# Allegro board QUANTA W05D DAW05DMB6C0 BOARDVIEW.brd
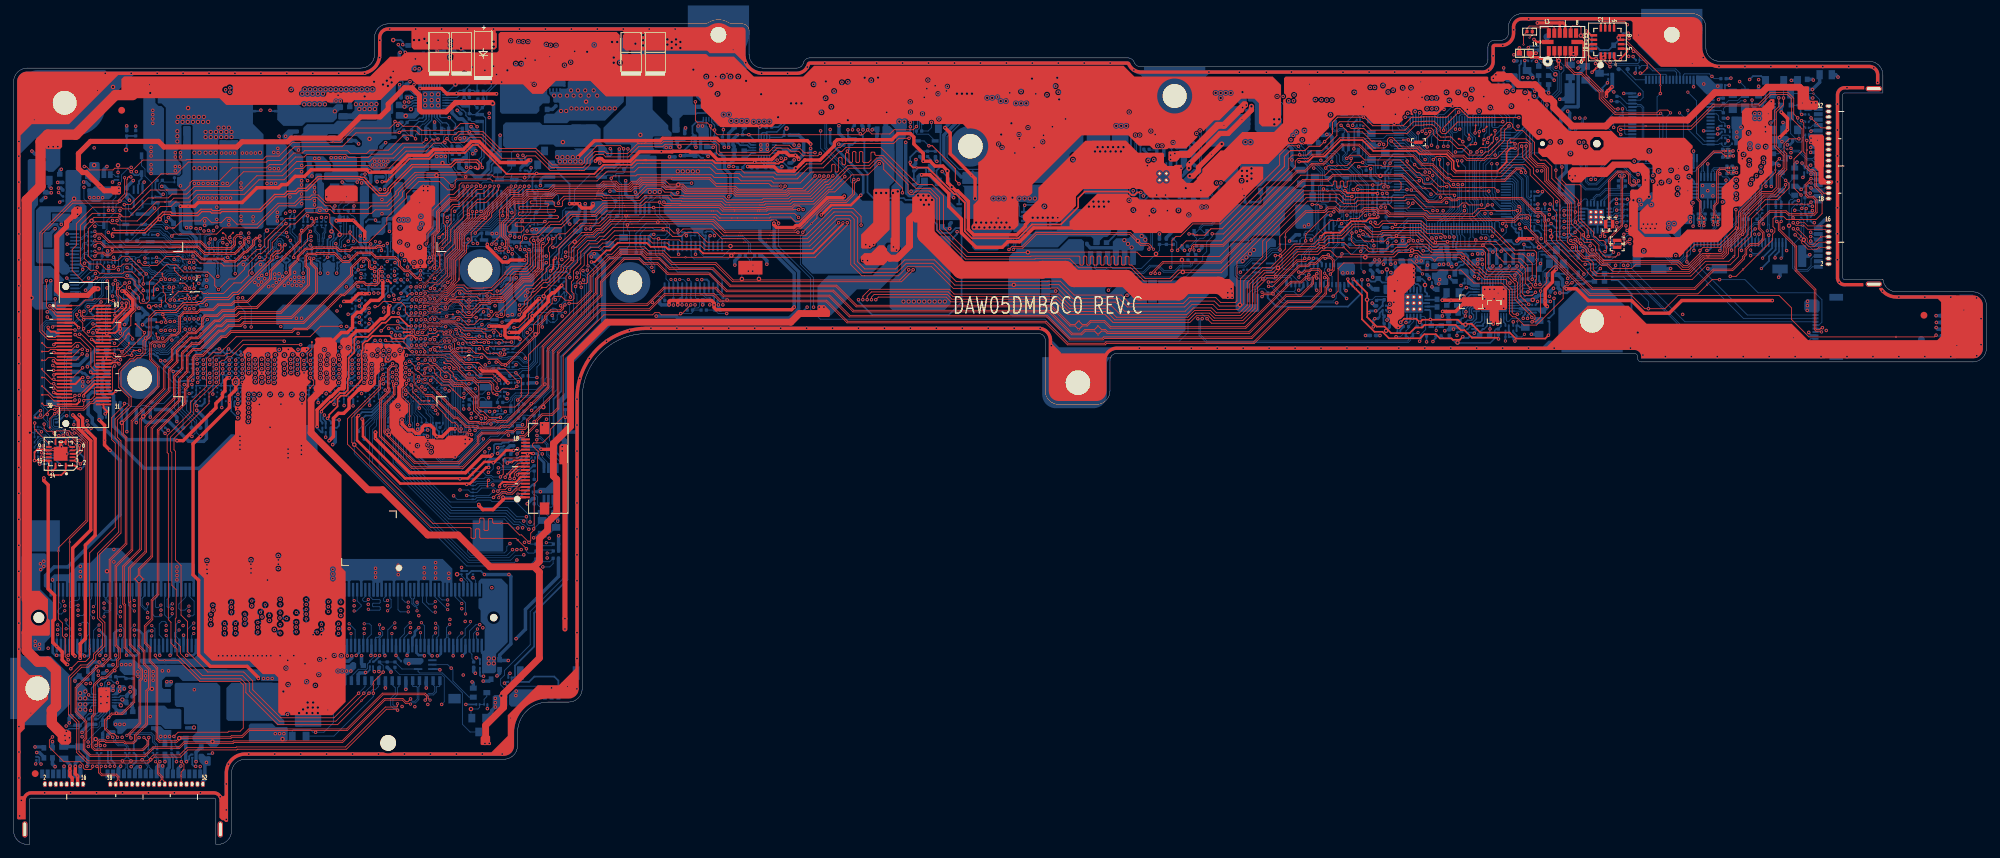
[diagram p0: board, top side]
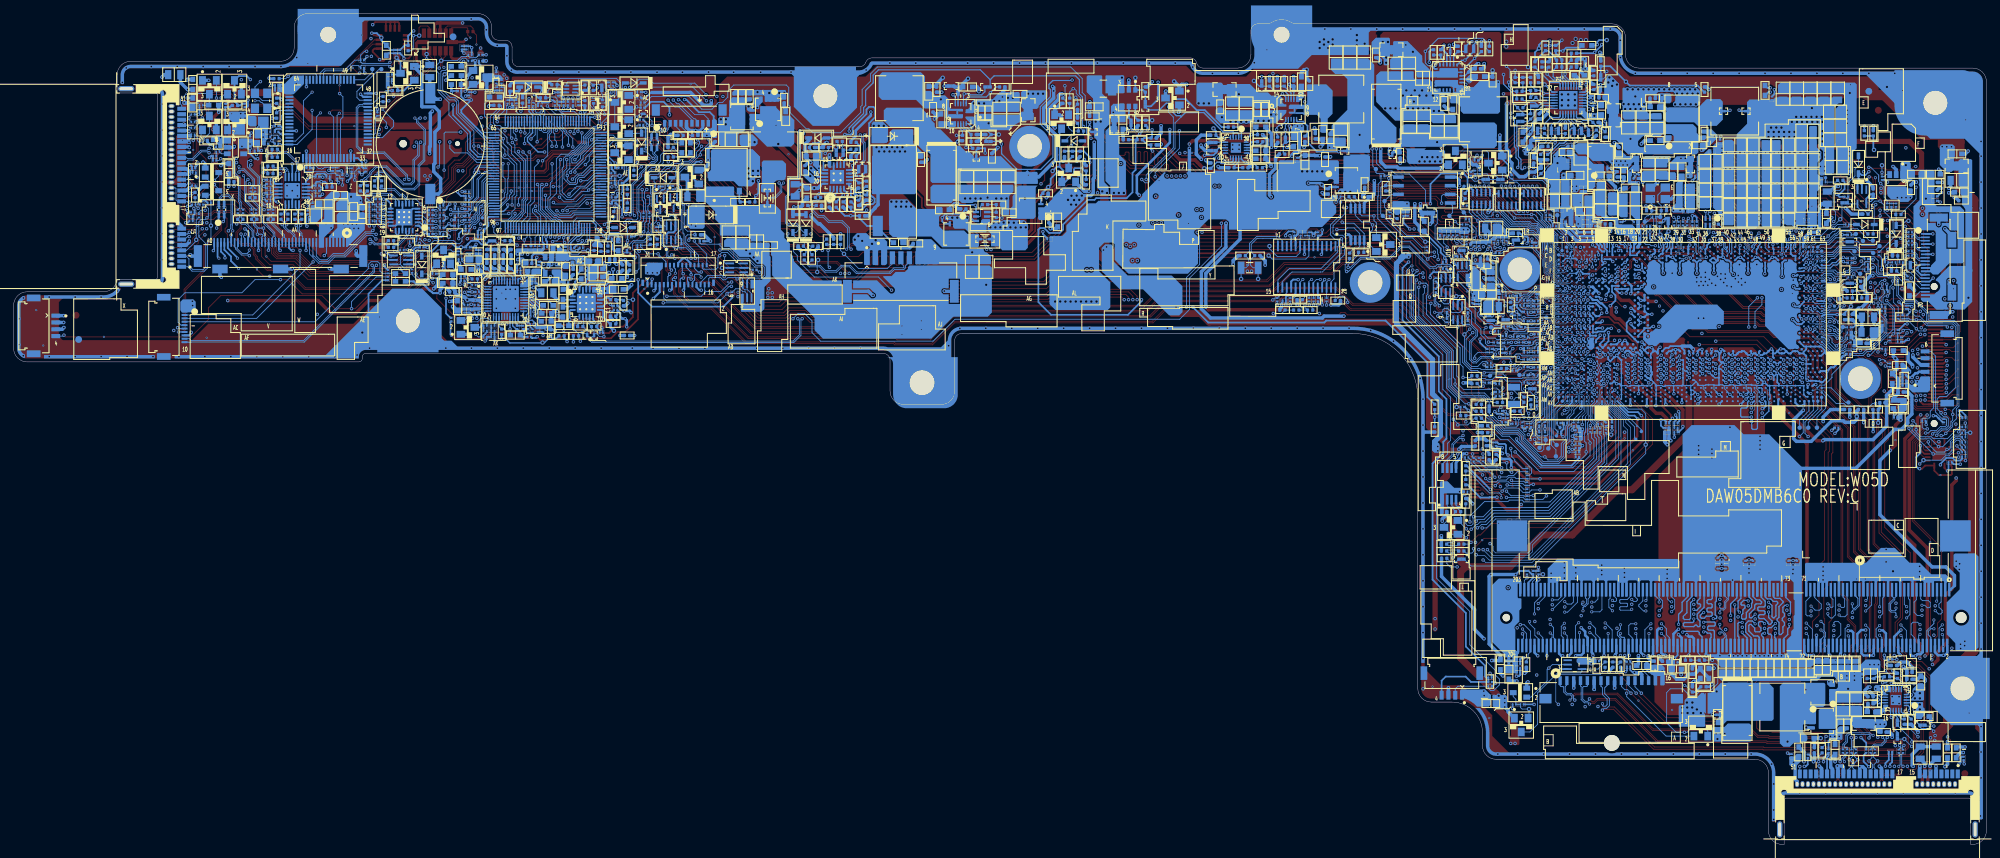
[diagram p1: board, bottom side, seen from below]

Outline 289.7 x 122 mm; copper layers: TOP, SGND, IN1, IN2, SVCC, BOTTOM. Coordinates in mm from the lower left corner of the outline.
Outline path: 0,112 arc(0.59,113.41) 2,114 51,114 arc(52.41,114.59) 53,116 53,118.5 arc(53.59,119.91) 55,120.5 101.43,120.5 arc(101.72,120.54) 101.99,120.67 arc(103.5,121.12) 105.02,120.67 arc(105.28,120.54) 105.57,120.5 107,120.5 arc(107.71,120.21) 108,119.5 108,116 arc(108.59,114.59) 110,114 115,114 arc(115.61,114.21) 115.97,114.75 arc(116.32,115.29) 116.94,115.5 163.63,115.5 arc(164.2,115.32) 164.56,114.85 arc(164.93,114.38) 165.5,114.2 215.5,114.2 arc(216.21,114.49) 216.5,115.2 216.5,117.1 arc(216.79,117.81) 217.5,118.1 218.5,118.1 arc(219.21,118.39) 219.5,119.1 219.5,120 arc(220.09,121.41) 221.5,122 246.5,122 arc(247.91,121.41) 248.5,120 248.5,117 arc(249.09,115.59) 250.5,115 272.5,115 arc(273.91,114.41) 274.5,113 274.5,110.35 268.9,110.35 arc(268.69,110.26) 268.6,110.05 268.6,83.25 arc(268.69,83.04) 268.9,82.95 274.51,82.95 arc(275.16,81.67) 276.5,81.15 287.7,81.15 arc(289.11,80.56) 289.7,79.15 289.7,72.85 arc(289.11,71.44) 287.7,70.85 239,70.85 arc(238.65,71) 238.5,71.35 238.5,71.6 arc(238.35,71.95) 238,72.1 162,72.1 arc(161.29,71.81) 161,71.1 161,66.6 arc(160.41,65.19) 159,64.6 153.5,64.6 arc(152.09,65.19) 151.5,66.6 151.5,74.02 arc(151.21,74.73) 150.5,75.02 93,75.02 arc(86.28,72.24) 83.5,65.52 83.5,22.9 arc(82.91,21.49) 81.5,20.9 78.5,20.9 arc(75.32,19.58) 74,16.4 74,14.5 arc(73.41,13.09) 72,12.5 34,12.5 arc(32.59,11.91) 32,10.5 32,2 arc(31.41,0.59) 30,0 29.7,0 29.7,6.5 arc(29.61,6.71) 29.4,6.8 2.6,6.8 arc(2.39,6.71) 2.3,6.5 2.3,0 2,0 arc(0.59,0.59) 0,2 0,112

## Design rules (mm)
constraint set DEFAULT: min track width 0.127
net group DFP-S7W7(8)-T1B: nets VCC_SENSE VSS_SENSE
net group T11B: nets DDR3_DRAMRST# SM_DRAMRST#
net group DFP-S3.5(4)W4.5-T12B: nets M_B_CLKN0 M_B_CLKN1 M_B_CLKP0 M_B_CLKP1
net group DFP-S3.5(4)W5-T12B: nets M_B_DQSN0 M_B_DQSN1 M_B_DQSN2 M_B_DQSN3 M_B_DQSN4 M_B_DQSN5 M_B_DQSN6 M_B_DQSN7 M_B_DQSP0 M_B_DQSP1 M_B_DQSP2 M_B_DQSP3 M_B_DQSP4 M_B_DQSP5 M_B_DQSP6 M_B_DQSP7
net group DFP-S4W5(4.5)-T1B: nets C_TX0_HDMI+ C_TX0_HDMI- C_TX1_HDMI+ C_TX1_HDMI- C_TX2_HDMI+ C_TX2_HDMI- C_TXC_HDMI+ C_TXC_HDMI- EDP_AUXN_R EDP_AUXP_R EDP_TXN0_R EDP_TXN1_R EDP_TXP0_R EDP_TXP1_R IN_CLK IN_CLK# IN_D0 IN_D0# IN_D1 IN_D1# IN_D2 IN_D2# INT_EDP_AUXN INT_EDP_AUXP INT_EDP_TXN0 INT_EDP_TXN1 INT_EDP_TXP0 INT_EDP_TXP1 MBCLK MBCLK2 MBDATA MBDATA2 SATA_RXN0_C SATA_RXN0_DC SATA_RXN0_DC_L SATA_RXN1 SATA_RXN1_C SATA_RXP0_C SATA_RXP0_DC SATA_RXP0_DC_L SATA_RXP1 SATA_RXP1_C SATA_TXN0 SATA_TXN0_C SATA_TXN0_DC SATA_TXN0_DC_L SATA_TXN1 SATA_TXN1_C SATA_TXP0 SATA_TXP0_C SATA_TXP0_DC SATA_TXP0_DC_L SATA_TXP1 SATA_TXP1_C SDVO_CLK SDVO_DATA SMB_ME0_CLK SMB_ME0_DAT SMB_ME1_CLK SMB_ME1_DAT SMB_PCH_CLK SMB_PCH_DAT SMB_RUN_CLK SMB_RUN_DAT USB30_RX1+ USB30_RX1+_C USB30_RX1+_DC USB30_RX1- USB30_RX1-_C USB30_RX1-_DC USB30_RX3+ USB30_RX3+_R USB30_RX3- USB30_RX3-_R USB30_TX1+ USB30_TX1+_C USB30_TX1+_DC USB30_TX1+_DC_C USB30_TX1- USB30_TX1-_C USB30_TX1-_DC USB30_TX1-_DC_C USB30_TX3+ USB30_TX3+_R USB30_TX3- USB30_TX3-_R USB+_CAMERA USB+_COMBO USB+_CR USB+_LEFT USB+_SENSOR USB+_TP USB+_TS USB+_WLAN USB-_CAMERA USB-_COMBO USB-_CR USB-_LEFT USB-_SENSOR USB-_TP USB-_TS USB-_WLAN USBP2+_C USBP2-_C USBP7+_C USBP7-_C
net group DFP-S4W5(4.5)-T12B: nets PCIE_RXN2_CARD PCIE_RXN3_WLAN PCIE_RXP2_CARD PCIE_RXP3_WLAN PCIE_TXN2_CARD PCIE_TXN2_CARD_C PCIE_TXN3_WLAN PCIE_TXN3_WLAN_C PCIE_TXP2_CARD PCIE_TXP2_CARD_C PCIE_TXP3_WLAN PCIE_TXP3_WLAN_C
net group DFP-S4W5-T12B: nets BQSRN BQSRP CSON CSOP SMC SMD
net group DFP-S8(5.5)W5(4.5)-T1B: nets CK_XDP_N CK_XDP_N_R CK_XDP_P CK_XDP_P_R CLK_PCIE_CRN CLK_PCIE_CRP CLK_PCIE_WLANN CLK_PCIE_WLANP
net group T1B: nets 3920_RST# +SMDDR_VREF_DIMM +SMDDR_VREF_DQ1 ALERT# CLK_24M_DEBUG CLK_24M_KBC CLK_PCI_EC_R CLK_PCI_LPC_R DDR_VTTREF DIGITAL_CLK DIGITAL_D1 DMIC0 DMIC_CLK_R DNBSWON# DNBSWON#_R EC_PECI EC_PECI_R EC_PWROK EC_RCIN# EXT_MIC_L FAN1_PWM FAN1SIG H_CPU_SVIDALRT# H_SYS_PWROK_XDP HOME_BUTTON_INT# HOME_BUTTON_SLEEP HPOUT_L HPOUT_L_1 HPOUT_R HPOUT_R_1 IMVP_PWRGD IMVP_PWRGD_R L_SPK+ L_SPK- LINEOUT_L LINEOUT_L_C LINEOUT_R LINEOUT_R_C MINICAR_PME# OVT_DETC PCH_INVRMEN PCH_OPI_RCOMP PCH_THRMTRIP# PCIE_CLKREQ0# PCIE_CLKREQ3# PCIE_CLKREQ4# PCIE_CLKREQ_WLAN# PCIE_WAKE# PM_THRMTRIP# R_SPK+ R_SPK- REQ_WLAN# RTC_RST# SATA_IREF SATA_RCOMP SENSE_A SENSE_A_1 SM_RCOMP_0 SM_RCOMP_1 SM_VREF SMDDR_VREF_DQ1_M1 SMDDR_VREF_DQ1_M3 SRTC_RST# SYS_PWROK SYS_RESET# THER_CPU THER_GPU THRM_ALERT_HW#1 VR_SVID_ALERT# VR_SVID_CLK VR_SVID_DATA VREFOUT_C XDP_BPM0 XDP_BPM1
net group T12B: nets 1237BSTPCH 1237ENPCH 1237FBPCH 1237FBPCH_S 1237PFMPCH 1237PGPCH 8008LX1.5V 51216DRVH 51216DRVL 51216MODE 51216PG 51216REFIN 51216S3 51216S5 51216SW 51216TRIP 51216VBST 51216VBST_S 51216VDDQSNS 81101_BST 81101_HG 81101_HG_G 81101_LG 81101_PH 81101COM 81101DIFFOUT 81101FB 81101ILIM 81101IOUT 81101ROSC 81101VCC 81101VRMP 81101VSN 81101VSP +0.75V_DDR_VTT +1.05V_S2 +1.8VREF +1.35VSUS_S +3.3VS5_S +3V_AVDD +3V_DEEP_SUS +3V_DVDD +3V_DVDD-IO +3V_RTC +3V_RTC_0 +3V_RTC_1 +3V_WLAN_P +3VLCD_CON +3VPCU +3VSPI +5VS5_S +12VALW +VCC_TS +VIN_1.05V +VIN_3VS5 +VIN_5VS5 +VIN_BLIGHT +VIN_DDR +VIN_VCC_CORE AC_LED_ON# ACIN ACZ_BCLK ACZ_RST# ACZ_RST#_AUDIO ACZ_SDIN0 ACZ_SDOUT ACZ_SDOUT_AUDIO ACZ_SPKR ACZ_SYNC ACZ_SYNC_AUDIO AD_AIR B_TEMP_MBAT BATDIS_G BATDIS_ID_DOD BIOS_CS# BIOS_RD# BIOS_SPI_CLK BIOS_WP# BIOS_WR# BIT_CLK_AUDIO BLON_CON BQACDRV BQB_1 BQB_2 BQBATDRV BQCLK BQCMSRC BQDATA BQHIDRV BQIOUT BQLODRV BQVCC CRY2 CSCOMP CSREF CSSUM EDP_RCOMP EMU_LID G5934CN G5934CP G5934DISC1 G5934DISC2 G5934DISC4 G5934PG GPIO33_EC H_PROCHOT# H_PROCHOT#_EC HD_SDIN0 IDEA_G LAD0 LAD1 LAD2 LAD3 LFRAME# M_B_DQ0 M_B_DQ1 M_B_DQ2 M_B_DQ3 M_B_DQ4 M_B_DQ5 M_B_DQ6 M_B_DQ7 M_B_DQ8 M_B_DQ9 M_B_DQ10 M_B_DQ11 M_B_DQ12 M_B_DQ13 M_B_DQ14 M_B_DQ15 M_B_DQ16 M_B_DQ17 M_B_DQ18 M_B_DQ19 M_B_DQ20 M_B_DQ21 M_B_DQ22 M_B_DQ23 M_B_DQ24 M_B_DQ25 M_B_DQ26 M_B_DQ27 M_B_DQ28 M_B_DQ29 M_B_DQ30 M_B_DQ31 M_B_DQ32 M_B_DQ33 M_B_DQ34 M_B_DQ35 M_B_DQ36 M_B_DQ37 M_B_DQ38 M_B_DQ39 M_B_DQ40 M_B_DQ41 M_B_DQ42 M_B_DQ43 M_B_DQ44 M_B_DQ45 M_B_DQ46 M_B_DQ47 M_B_DQ48 M_B_DQ49 M_B_DQ50 M_B_DQ51 M_B_DQ52 M_B_DQ53 M_B_DQ54 M_B_DQ55 M_B_DQ56 M_B_DQ57 M_B_DQ58 M_B_DQ59 M_B_DQ60 M_B_DQ61 M_B_DQ62 M_B_DQ63 M_B_ODT0 M_B_ODT1 MBATLED0# NB670BST NB670BST_S NB670EN NB670ENLDO NB670PG NB670SW NB670VOUT NB671BST NB671BST_S NB671EN NB671FB NB671PG NB671SW PCH_DPST_PWM PCH_DPST_PWM_R PCH_EDP_BLON PCH_SPI1_CLK PCH_SPI1_CLK_R PCH_SPI1_SI PCH_SPI1_SI_R PCH_SPI1_SO PCH_SPI1_SO_R PCH_SPI_CS0# PCH_SPI_CS0#_R PCH_SPI_IO2 PCH_SPI_IO3 PCIE_CLKREQ_CR# PCIE_IREF PCIE_RCOMP PROCHOT# REGN6V RTC_X1 RTC_X2 SM_INTRUDER# SM_RCOMP_2 SPKR SWN SYS_I TEMP_MBAT THRM_MOINTOR THRM_MOINTOR1 TSENSE VBOOT VR_HOT# VR_RDY XCLK_BIASREF XTAL24_IN XTAL24_OUT
net group TB: nets CATERR#
net group W4.5(5)-T1B: nets PLTRST#
net group W5(4.5)-T1B: nets I2C0_SCL I2C0_SDA I2C1_SCL I2C1_SDA SDIO_CLK SDIO_CMD SDIO_D1 SDIO_D2 SDIO_D3
net group W7.5(8)-T12B: nets M_B_A0 M_B_A1 M_B_A2 M_B_A3 M_B_A4 M_B_A5 M_B_A6 M_B_A7 M_B_A8 M_B_A9 M_B_A10 M_B_A11 M_B_A12 M_B_A13 M_B_A14 M_B_A15 M_B_BS#0 M_B_BS#1 M_B_BS#2 M_B_CAS# M_B_CKE0 M_B_CKE1 M_B_CS#0 M_B_CS#1 M_B_RAS# M_B_WE#

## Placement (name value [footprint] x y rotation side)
C1  0.22u/10v_4  [CC0402]  222.62 119.36 180 top
C2  10u/6.3v_6  [CC0603]  221.86 116.18 180 top
C3  0.1u/10v_2  [CC0201_S]  223.87 116.97 90 bottom
C4  0.1u/10v_2  [CC0201_S]  223.21 116.97 90 bottom
C5  *0.1u/10v_2  [CC0201_S]  46.86 60.53 180 bottom
C8  4.7u/25v_8  [CC0805]  228.59 113.57 90 bottom
C9  1u/6.3v_2  [CC0201_S]  218.81 113.14 270 bottom
C11  10u/6.3vs_6  [CC0603]  263.39 111.61 270 bottom
C12  4.7u/6.3v_6  [CC0603]  224.68 111.59 180 bottom
C13  0.1u/10v_2  [CC0201_S]  251.07 111.49 0 bottom
C14  0.047uf_4  [CC0402]  205.81 111.13 270 bottom
C15  1u/6.3v_2  [CC0201_S]  218.69 110.95 90 bottom
C16  1u/6.3v_2  [CC0201_S]  218.05 110.95 90 bottom
C17  0.1u/10v_2  [CC0201_S]  251.07 110.72 0 bottom
C18  0.1u/10v_2  [CC0201_S]  224.2 110.65 180 bottom
C19  220p/25v_2  [CC0201_S]  197.86 110.47 0 bottom
C20  22u/6.3vt_8  [CC0805]  27.86 110.24 270 bottom
C21  *22u/6.3vs_8  [CC0805]  25.85 110.24 270 bottom
C22  0.1u/10v_2  [CC0201_S]  222.8 110.22 90 bottom
C23  0.1u/10v_2  [CC0201_S]  209.77 110.19 270 bottom
C24  100p/50v_4  [CC0402]  214.95 109.25 270 bottom
C25  12p/50v_4  [CC0402]  251.07 109.2 90 bottom
C26  0.1u/10v_2  [CC0201_S]  216.53 109.05 270 bottom
C27  10u/6.3vs_6  [CC0603]  263.39 108.87 270 bottom
C28  0.1u/25v_4  [CC0402]  205.81 108.84 270 bottom
C29  0.1u/10v_2  [CC0201_S]  209.54 108.79 270 bottom
C30  0.1u/10v_2  [CC0201_S]  208.93 108.79 270 bottom
C31  0.1u/10v_2  [CC0201_S]  208.32 108.79 270 bottom
C32  0.1u/10v_2  [CC0201_S]  207.56 108.79 270 bottom
C33  0.01u/16v_2  [CC0201_S]  206.82 108.79 270 bottom
C34  0.1u/10v_2  [CC0201_S]  258.61 108.51 90 bottom
C35  22u/6.3vt_8  [CC0805]  22.22 107.55 0 bottom
C36  12p/50v_4  [CC0402]  251.07 107.04 270 bottom
C37  0.1u/10v_2  [CC0201_S]  251.07 105.52 180 bottom
C38  0.1u/10v_2  [CC0201_S]  251.07 104.63 0 bottom
C39  100p/50v_4  [CC0402]  191.76 104.12 0 bottom
C40  100p/50v_4  [CC0402]  189.6 104.12 180 bottom
C41  0.1u/10v_2  [CC0201_S]  254.98 103.71 90 bottom
C42  1000p/50v_4  [CC0402]  186.68 103.61 90 bottom
C43  0.1u/10v_4  [CC0402]  126.36 103.48 0 bottom
C44  1u/6.3v_4  [CC0402]  260.88 103.38 180 bottom
C45  0.1u/10v_4  [CC0402]  122.29 102.72 180 bottom
C46  22u/6.3vt_8  [CC0805]  36.95 102.72 180 bottom
C47  22u/6.3vt_8  [CC0805]  33.39 102.72 0 bottom
C48  22u/6.3vt_8  [CC0805]  29.84 102.72 180 bottom
C49  22u/6.3vt_8  [CC0805]  26.28 102.72 0 bottom
C50  *1u/6.3v_2  [CC0201_S]  61.13 102.6 0 bottom
C51  *33p/50v_4  [CC0402]  193.21 102.34 180 bottom
C52  *0.01u/10v_4  [CC0402]  251.35 102.06 0 bottom
C53  1u/6.3v_2  [CC0201_S]  254.07 101.88 180 bottom
C54  0.1u/50v_6  [CC0603]  4.34 101.4 180 bottom
C55  *220p/25v_2  [CC0201_S]  260.19 101.1 180 bottom
C56  *33p/50v_4  [CC0402]  193.21 100.94 180 bottom
C57  *0.01u/10v_4  [CC0402]  251.35 100.92 0 bottom
C58  1u/6.3v_2  [CC0201_S]  61.13 100.46 0 bottom
C59  22u/6.3vt_8  [CC0805]  36.95 100.44 180 bottom
C60  22u/6.3vt_8  [CC0805]  33.39 100.44 0 bottom
C61  22u/6.3vt_8  [CC0805]  29.84 100.44 180 bottom
C62  22u/6.3vt_8  [CC0805]  26.28 100.44 0 bottom
C63  22u/6.3vt_8  [CC0805]  40.51 100.31 0 bottom
C64  *0.01u/10v_4  [CC0402]  251.99 99.6 0 bottom
C65  0.1u/10v_2  [CC0201_S]  201.64 99.37 0 bottom
C66  *47p/25v_2  [CC0201_S]  200.6 99.37 0 bottom
C67  0.1u/10v_2  [CC0201_S]  246.45 99.34 0 bottom
C68  0.1u/10v_2  [CC0201_S]  263.26 99.29 180 bottom
C69  *10u/6.3v_6  [CC0603]  258.11 99.24 270 bottom
C70  47u/6.3vst_8  [CC0805]  49.65 99.07 270 bottom
C71  47u/6.3vst_8  [CC0805]  47.62 99.07 270 bottom
C72  0.1u/10v_2  [CC0201_S]  237.99 99.04 270 bottom
C73  0.01u/16v_2  [CC0201_S]  263.19 98.66 180 bottom
C74  *0.01u/10v_4  [CC0402]  251.99 98.51 0 bottom
C75  *10u/6.3v_6  [CC0603]  7.51 98.4 0 bottom
C76  1u/6.3v_2  [CC0201_S]  43.05 98.15 180 bottom
C77  22u/6.3vt_8  [CC0805]  40.51 98.15 0 bottom
C78  22u/6.3vt_8  [CC0805]  36.95 98.15 180 bottom
C79  22u/6.3vt_8  [CC0805]  33.39 98.15 0 bottom
C80  22u/6.3vt_8  [CC0805]  29.84 98.15 180 bottom
C81  22u/6.3vt_8  [CC0805]  26.28 98.15 0 bottom
C82  1u/6.3v_2  [CC0201_S]  51.05 98.1 270 bottom
C83  0.1u/10v_2  [CC0201_S]  245.1 98.07 0 bottom
C84  1u/6.3v_2  [CC0201_S]  243.53 98.07 0 bottom
C85  1u/6.3v_2  [CC0201_S]  51.81 97.52 90 bottom
C86  *4.7u/25v_8  [CC0805]  4.36 97.52 180 bottom
C87  0.1u/10v_4  [CC0402]  257.73 97.34 0 bottom
C88  *0.047u/10v_4  [CC0402]  7.59 97.21 180 bottom
C89  0.1u/10v_2  [CC0201_S]  201.67 97.13 180 bottom
C90  *0.1u/10v_4  [CC0402]  236.69 97.06 90 bottom
C91  *0.1u/10v_4  [CC0402]  235.68 97.06 90 bottom
C92  *0.1u/10v_2  [CC0201_S]  263.24 96.75 180 bottom
C93  22u/6.3vst_8  [CC0805]  62.6 96.63 0 bottom
C94  1u/6.3v_4  [CC0402]  11.07 96.45 90 bottom
C95  *47u/6.3vst_8  [CC0805]  44.19 96.37 0 bottom
C96  *0.1u/10v_4  [CC0402]  238.78 96.35 90 bottom
C97  *0.1u/10v_4  [CC0402]  237.76 96.35 90 bottom
C98  22p/50v_4  [CC0402]  88.21 96.35 90 bottom
C99  1u/6.3v_2  [CC0201_S]  59.48 96.2 270 bottom
C100  *1u/6.3v_2  [CC0201_S]  58.87 96.2 270 bottom
C101  0.1u/10v_2  [CC0201_S]  254.88 96.12 90 bottom
C102  0.1u/10v_2  [CC0201_S]  254.25 96.12 90 bottom
C103  22u/6.3vt_8  [CC0805]  40.51 96.12 0 bottom
C104  *0.047u/10v_4  [CC0402]  7.61 96.09 180 bottom
C105  22u/6.3vt_8  [CC0805]  36.95 95.99 180 bottom
C106  *22u/6.3vs_8  [CC0805]  33.39 95.99 0 bottom
C107  *22u/6.3vs_8  [CC0805]  29.84 95.99 180 bottom
C108  22u/6.3vt_8  [CC0805]  26.28 95.99 0 bottom
C109  *0.1u/10v_4  [CC0402]  16.63 95.86 90 bottom
C110  0.1u/50v_6  [CC0603]  3.95 95.79 0 bottom
C111  0.01u/25v_4  [CC0402]  241.67 95.36 0 bottom
C112  *10p/25v_2  [CC0201_S]  223.08 95.23 180 bottom
C113  0.01u/16v_2  [CC0201_S]  7.54 95.15 0 bottom
C114  2200p/50v_4  [CC0402]  93.21 95.1 180 bottom
C115  0.01u/25v_4  [CC0402]  91.18 95.1 180 bottom
C116  22u/6.3vs_8  [CC0805]  55.87 95.08 180 bottom
C117  47u/6.3vst_8  [CC0805]  52.32 94.77 180 bottom
C118  *0.1u/10v_2  [CC0201_S]  236.21 94.75 0 bottom
C119  *10p/25v_2  [CC0201_S]  223.08 94.59 180 bottom
C120  *22u/6.3vs_8  [CC0805]  59.25 94.57 180 bottom
C121  .01u/25v_4  [CC0402]  3.68 94.54 180 bottom
C122  *0.01u/16v_2  [CC0201_S]  7.54 94.52 180 bottom
C123  22u/6.3vs_8  [CC0805]  62.7 94.44 0 bottom
C124  *47u/6.3vst_8  [CC0805]  44.19 94.34 0 bottom
C125  0.1u/10v_2  [CC0201_S]  201.59 94.14 0 bottom
C126  0.1u/50v_6  [CC0603]  244.09 94.09 0 bottom
C127  22u/6.3vt_8  [CC0805]  40.51 94.09 0 bottom
C128  *33p/25v_2  [CC0201_S]  263.24 93.93 180 bottom
C129  22u/6.3vt_8  [CC0805]  36.95 93.83 180 bottom
C130  22u/6.3vt_8  [CC0805]  33.39 93.83 0 bottom
C131  22u/6.3vt_8  [CC0805]  29.84 93.83 180 bottom
C132  22u/6.3vt_8  [CC0805]  26.28 93.83 0 bottom
C133  *10p/50v_4  [CC0402]  199.59 93.81 90 bottom
C134  *10p/25v_2  [CC0201_S]  223.08 93.32 180 bottom
C135  1u/6.3v_2  [CC0201_S]  62.6 93.07 0 bottom
C136  22u/6.3vs_8  [CC0805]  55.87 93.07 180 bottom
C137  12p/50v_4  [CC0402]  49.52 93.07 180 bottom
C138  12p/50v_4  [CC0402]  47.36 93.07 0 bottom
C139  10u/6.3vs_6  [CC0603]  59.02 92.97 180 bottom
C140  0.1u/10v_2  [CC0201_S]  256.79 92.94 90 bottom
C141  0.1u/10v_2  [CC0201_S]  256.02 92.94 90 bottom
C142  0.1u/10v_2  [CC0201_S]  254.75 92.94 90 bottom
C143  0.1u/10v_2  [CC0201_S]  254.12 92.94 90 bottom
C144  0.1u/10v_2  [CC0201_S]  252.34 92.94 90 bottom
C145  0.1u/10v_2  [CC0201_S]  251.58 92.94 90 bottom
C146  *4.7u/25v_8  [CC0805]  241.6 92.94 270 bottom
C147  0.1u/50v_6  [CC0603]  239.77 92.94 90 bottom
C148  0.01u/25v_4  [CC0402]  238.5 92.94 270 bottom
C149  1u/6.3v_2  [CC0201_S]  44.19 92.94 0 bottom
C150  0.1u/10v_2  [CC0201_S]  263.36 92.82 0 bottom
C151  47u/6.3vs_8  [CC0805]  52.32 92.77 180 bottom
C152  0.1u/10v_2  [CC0201_S]  85.59 92.56 90 bottom
C153  1u/6.3v_2  [CC0201_S]  84.96 92.56 270 bottom
C154  *10p/50v_4  [CC0402]  17.77 92.56 0 bottom
C155  *10p/25v_2  [CC0201_S]  223.08 92.33 180 bottom
C156  *4.7u/25v_8  [CC0805]  244.47 92.31 180 bottom
C157  0.1u/10v_2  [CC0201_S]  263.64 92.18 0 bottom
C158  *0.01u/10v_4  [CC0402]  250.44 92.18 90 bottom
C159  *0.01u/10v_4  [CC0402]  249.42 92.18 90 bottom
C160  *0.01u/10v_4  [CC0402]  248.4 92.18 90 bottom
C161  *0.01u/10v_4  [CC0402]  247.39 92.18 90 bottom
C162  1u/6.3v_2  [CC0201_S]  58.89 92 180 bottom
C163  4.7u/6.3v_6  [CC0603]  23.49 91.93 90 bottom
C164  22u/6.3vt_8  [CC0805]  36.95 91.67 180 bottom
C165  *22u/6.3vs_8  [CC0805]  33.39 91.67 0 bottom
C166  22u/6.3vt_8  [CC0805]  29.84 91.67 180 bottom
C167  0.1u/10v_2  [CC0201_S]  263.64 91.55 0 bottom
C168  1u/6.3v_2  [CC0201_S]  58.89 91.39 180 bottom
C169  1u/6.3v_2  [CC0201_S]  53.99 91.39 180 bottom
C170  1u/6.3v_2  [CC0201_S]  51.5 91.39 180 bottom
C171  0.1u/10v_2  [CC0201_S]  45.84 91.17 270 bottom
C172  0.1u/10v_2  [CC0201_S]  45.2 91.17 270 bottom
C173  0.1u/10v_2  [CC0201_S]  44.57 91.17 270 bottom
C174  0.1u/10v_2  [CC0201_S]  43.93 91.17 270 bottom
C175  1u/6.3v_2  [CC0201_S]  58.89 90.78 180 bottom
C176  1u/6.3v_2  [CC0201_S]  57.7 90.78 0 bottom
C177  22u/6.3vst_8  [CC0805]  72.71 90.51 0 bottom
C178  0.1u/10v_2  [CC0201_S]  11.17 89.9 180 bottom
C179  0.1u/10v_2  [CC0201_S]  221.28 89.82 180 bottom
C180  *0.1u/10v_2  [CC0201_S]  228.47 89.64 180 bottom
C181  *0.1u/10v_2  [CC0201_S]  101.62 89.64 270 bottom
C182  *0.1u/10v_2  [CC0201_S]  98.16 89.64 270 bottom
C183  0.1u/10v_2  [CC0201_S]  11.17 89.26 180 bottom
C184  0.1u/10v_2  [CC0201_S]  221.28 89.18 180 bottom
C185  0.1u/10v_2  [CC0201_S]  202.1 88.96 180 bottom
C186  *0.1u/10v_2  [CC0201_S]  67.56 88.83 180 bottom
C187  *0.1u/10v_4  [CC0402]  234.28 88.65 180 bottom
C188  0.1u/10v_2  [CC0201_S]  11.17 88.63 180 bottom
C189  0.01u/25v_2  [CC0201_S]  197.86 87.99 0 bottom
C190  0.1u/10v_2  [CC0201_S]  11.17 87.99 180 bottom
C191  4.7u/6.3v_6  [CC0603]  200.91 87.91 270 bottom
C192  0.1u/10v_2  [CC0201_S]  211.6 87.74 0 bottom
C193  *0.1u/10v_4  [CC0402]  234.28 87.69 180 bottom
C194  0.1u/10v_2  [CC0201_S]  222.98 87.69 180 bottom
C195  0.1u/10v_2  [CC0201_S]  207.64 87.61 0 bottom
C196  0.047u/10v_4  [CC0402]  210.03 87.51 180 bottom
C197  *22p/50v_4  [CC0402]  203.45 87.48 90 bottom
C198  0.1u/10v_2  [CC0201_S]  11.17 87.1 180 bottom
C199  1u/6.3v_2  [CC0201_S]  221.78 87.03 270 bottom
C200  0.1u/10v_2  [CC0201_S]  221.15 87.03 270 bottom
C201  0.1u/10v_2  [CC0201_S]  208.65 87.48 270 bottom
C202  *12p  [CC0402]  109.21 86.47 180 bottom
C203  *12p  [CC0402]  107.05 86.47 0 bottom
C204  0.1u/10v_2  [CC0201_S]  11.17 86.47 180 bottom
C205  22p/50v_4  [CC0402]  13.4 86.42 0 bottom
C206  *1000p/50v_4  [CC0402]  201.8 85.96 0 bottom
C207  1u/6.3v_2  [CC0201_S]  207.64 85.83 90 bottom
C208  *10p/50v_4  [CC0402]  73.27 85.58 90 bottom
C209  1u/6.3v_2  [CC0201_S]  212.59 85.32 270 bottom
C210  2200p/50v_4  [CC0402]  220.21 84.94 270 bottom
C211  2200p/50v_4  [CC0402]  219.07 84.94 270 bottom
C212  2200p/50v_4  [CC0402]  217.8 84.94 270 bottom
C213  2200p/50v_4  [CC0402]  216.65 84.94 270 bottom
C214  *1000p/50v_4  [CC0402]  200.27 84.71 270 bottom
C215  *1000p/50v_4  [CC0402]  199.26 84.71 270 bottom
C216  1u/6.3v_2  [CC0201_S]  215.51 84.64 180 bottom
C217  1u/25v_6  [CC0603]  203.9 84.51 180 bottom
C218  4.7u/6.3v_6  [CC0603]  223.26 84.43 180 bottom
C219  22p/50v_4  [CC0402]  13.56 84.21 180 bottom
C220  0.1u/10v_2  [CC0201_S]  234.74 84.1 90 bottom
C221  *1000p/50v_4  [CC0402]  207.54 84.05 270 bottom
C222  0.1u/10v_2  [CC0201_S]  215.51 84.03 180 bottom
C223  1u/25v_8s  [CC0603]  206.34 83.77 90 bottom
C224  10p/25v_2  [CC0201_S]  223.77 83.42 180 bottom
C225  1u/10v_6  [CC0603]  203.9 83.34 180 bottom
C226  1u/25v_6  [CC0603]  201.11 83.11 180 bottom
C227  1u/6.3v_2  [CC0201_S]  213.33 83.04 0 bottom
C228  10p/25v_2  [CC0201_S]  223.77 82.78 180 bottom
C229  2.2u/6.3v_6  [CC0603]  210.94 82.68 0 bottom
C230  220p/25v_2  [CC0201_S]  234.74 83.09 90 bottom
C231  0.1u/10v_2  [CC0201_S]  208.53 82.53 0 bottom
C232  0.1u/10v_2  [CC0201_S]  213.33 82.4 0 bottom
C233  1u/6.3v_2  [CC0201_S]  71.57 81.64 90 bottom
C234  1u/25v_8s  [CC0603]  200.91 81.51 180 bottom
C235  *0.1u/10v_4  [CC0402]  20.06 81.26 0 bottom
C236  0.1u/10v_4  [CC0402]  225.29 81.13 180 bottom
C237  *10p/25v_2  [CC0201_S]  221.61 81.13 0 bottom
C238  4.7u/25v_8  [CC0805]  211.32 81.01 180 bottom
C239  *33p/25v_2  [CC0201_S]  222.93 80.9 90 bottom
C240  1u/10v_8s  [CC0603]  209.03 80.78 270 bottom
C241  0.1u/10v_2  [CC0201_S]  71.57 80.62 270 bottom
C242  *0.1u/10v_2  [CC0201_S]  98.16 79.99 90 bottom
C243  *0.1u/10v_2  [CC0201_S]  103.12 79.86 180 bottom
C244  1u/6.3v_2  [CC0201_S]  75.48 79.76 270 bottom
C245  *0.1u/10v_2  [CC0201_S]  74.87 79.58 270 bottom
C246  *1000p/50v_4  [CC0402]  200.14 79.48 270 bottom
C247  *33p/25v_2  [CC0201_S]  223.26 79.23 0 bottom
C248  2.2u/6.3v_6  [CC0603]  211.19 79.15 0 bottom
C249  22u/6.3vst_8  [CC0805]  72.51 78.97 180 bottom
C250  0.1u/10v_2  [CC0201_S]  11.8 78.87 90 bottom
C251  *10p/50v_4  [CC0402]  103.37 78.47 0 bottom
C252  0.1u/10v_2  [CC0201_S]  223.51 78.34 90 bottom
C253  1u/6.3v_2  [CC0201_S]  222.88 78.34 90 bottom
C254  1u/10v_8s  [CC0603]  209.03 78.19 90 bottom
C255  *10p/25v_2  [CC0201_S]  221.73 78.08 0 bottom
C256  2.2u/6.3v_6  [CC0603]  211.4 77.98 180 bottom
C257  *1000p/50v_4  [CC0402]  201.67 77.58 0 bottom
C258  *1u/6.3v_4  [CC0402]  19.68 77.45 90 bottom
C259  *22u/6.3v_8  [CC0805]  17.39 77.45 0 bottom
C260  0.1u/10v_2  [CC0201_S]  11.68 77.45 90 bottom
C261  2.2u/6.3v_6  [CC0603]  211.5 76.81 180 bottom
C262  0.1u/10v_2  [CC0201_S]  15.28 76.56 90 bottom
C263  0.1u/10v_2  [CC0201_S]  219.32 76.18 0 bottom
C264  1u/25v_8s  [CC0603]  208.91 76.18 0 bottom
C265  1u/6.3v_2  [CC0201_S]  214.88 75.93 90 bottom
C266  1u/6.3v_2  [CC0201_S]  214.22 75.93 90 bottom
C267  1u/6.3v_2  [CC0201_S]  213.48 75.39 90 bottom
C268  1u/6.3v_2  [CC0201_S]  212.74 75.52 90 bottom
C269  0.1u/10v_2  [CC0201_S]  212.08 75.52 90 bottom
C270  0.1u/10v_2  [CC0201_S]  220.46 75.42 0 bottom
C271  0.01u/25v_2  [CC0201_S]  219.32 75.42 0 bottom
C272  2.2u/6.3v_6  [CC0603]  216.02 74.78 0 bottom
C273  *1000p/50v_4  [CC0402]  199.61 74.73 0 bottom
C274  0.1u/10v_2  [CC0201_S]  12.79 73.82 180 bottom
C275  *0.1u/10v_2  [CC0201_S]  70.81 72.73 180 bottom
C276  220p/25v_2  [CC0201_S]  12.06 68.94 180 bottom
C277  0.1u/10v_2  [CC0201_S]  12.06 68.05 0 bottom
C278  10p/25v_4  [CC0402]  66.9 64.93 90 bottom
C279  0.022u/6.3v_4  [CC0402]  15.26 64.88 180 bottom
C280  *2.2u/6.3v_6  [CC0603]  12.95 64.01 180 bottom
C281  10p/25v_4  [CC0402]  68.9 63.63 180 bottom
C282  *0.1u/10v_2  [CC0201_S]  13.33 62.69 180 bottom
C283  220p/25v_2  [CC0201_S]  9.19 62.21 0 bottom
C284  220p/25v_2  [CC0201_S]  6.22 62.21 90 bottom
C285  0.1u/10v_2  [CC0201_S]  46.83 61.83 180 bottom
C286  1u/6.3v_2  [CC0201_S]  45.59 61.83 0 bottom
C287  *1u/6.3v_2  [CC0201_S]  54.98 61.7 90 bottom
C288  1u/6.3v_2  [CC0201_S]  46.86 61.17 0 bottom
C289  0.1u/10v_2  [CC0201_S]  45.59 61.17 180 bottom
C290  0.1u/10v_2  [CC0201_S]  60.06 60.81 180 bottom
C291  1u/6.3v_2  [CC0201_S]  45.59 60.53 0 bottom
C292  1u/6.3v_2  [CC0201_S]  59.94 60.18 180 bottom
C293  0.1u/10v_2  [CC0201_S]  59.94 59.54 180 bottom
C294  1u/6.3v_2  [CC0201_S]  72.03 58.78 90 bottom
C295  0.1u/10v_2  [CC0201_S]  5.33 56.11 180 bottom
C296  *10p/50v_4  [CC0402]  76.45 50.4 90 bottom
C297  *0.01u/16v_4  [CC0402]  79.62 48.87 0 bottom
C298  *2200p/50v_4  [CC0402]  77.59 48.87 0 bottom
C299  1u/6.3v_2  [CC0201_S]  39.49 41.76 270 bottom
C300  1u/6.3v_2  [CC0201_S]  38.22 41.76 270 bottom
C301  1u/6.3v_2  [CC0201_S]  35.43 41.38 270 bottom
C302  1u/6.3v_2  [CC0201_S]  34.28 41.38 270 bottom
C303  1u/6.3v_2  [CC0201_S]  29.08 41.38 270 bottom
C304  1u/6.3v_2  [CC0201_S]  27.81 41.38 270 bottom
C305  1u/6.3v_2  [CC0201_S]  39.49 40.75 90 bottom
C306  1u/6.3v_2  [CC0201_S]  38.22 40.75 90 bottom
C307  0.1u/10v_2  [CC0201_S]  66.57 39.91 270 bottom
C308  1u/6.3v_2  [CC0201_S]  68.71 27.16 0 bottom
C309  *0.1u/10v_2  [CC0201_S]  14.09 27.16 0 bottom
C310  *0.1u/10v_2  [CC0201_S]  57.14 26.9 0 bottom
C311  *220p/25v_2  [CC0201_S]  52.54 26.83 180 bottom
C312  *0.1u/10v_2  [CC0201_S]  45.61 26.73 0 bottom
C313  1u/6.3v_2  [CC0201_S]  68.71 26.52 0 bottom
C314  0.1u/10v_4  [CC0402]  48.76 26.52 270 bottom
C315  2.2u/6.3v_4  [CC0402]  22.34 26.52 90 bottom
C316  2.2u/6.3v_4  [CC0402]  21.33 26.52 90 bottom
C317  2.2u/6.3v_4  [CC0402]  20.31 26.52 90 bottom
C318  2.2u/6.3v_4  [CC0402]  19.22 26.52 90 bottom
C319  2.2u/6.3v_6  [CC0603]  71.37 26.4 90 bottom
C320  *10u/6.3v_6  [CC0603]  50.61 26.27 180 bottom
C321  10u/6.3v_6  [CC0603]  24.68 26.27 90 bottom
C322  10u/6.3v_6  [CC0603]  23.49 26.27 90 bottom
C323  0.1u/10v_2  [CC0201_S]  52.54 26.12 0 bottom
C324  1u/6.3v_2  [CC0201_S]  68.71 25.89 0 bottom
C325  10u/6.3v_6  [CC0603]  38.8 25.89 90 bottom
C326  10u/6.3v_6  [CC0603]  37.63 25.89 90 bottom
C327  10u/6.3v_6  [CC0603]  36.47 25.89 90 bottom
C328  10u/6.3v_6  [CC0603]  35.27 25.89 90 bottom
C329  10u/6.3v_6  [CC0603]  34.1 25.89 90 bottom
C330  10u/6.3v_6  [CC0603]  32.94 25.89 90 bottom
C331  10u/6.3v_6  [CC0603]  31.77 25.89 90 bottom
C332  10u/6.3v_6  [CC0603]  30.6 25.89 90 bottom
C333  10u/6.3v_6  [CC0603]  29.43 25.89 90 bottom
C334  10u/6.3v_6  [CC0603]  28.26 25.89 90 bottom
C335  10u/6.3v_6  [CC0603]  27.07 25.89 90 bottom
C336  10u/6.3v_6  [CC0603]  25.87 25.89 90 bottom
C337  *2.2u/6.3v_6  [CC0603]  45.51 25.76 0 bottom
C338  1u/6.3v_2  [CC0201_S]  68.71 25.25 0 bottom
C339  10u/6.3v_6  [CC0603]  70.12 25 90 bottom
C340  *220p/25v_2  [CC0201_S]  72.89 23.86 0 bottom
C341  *220p/25v_2  [CC0201_S]  72.89 23.22 0 bottom
C342  0.022u/6.3v_4  [CC0402]  43.17 22.76 90 bottom
C343  0.1u/10v_2  [CC0201_S]  72.64 21.7 180 bottom
C344  10u/6.3vs_6  [CC0603]  72.76 20.68 0 bottom
C345  0.1u/10v_2  [CC0201_S]  69.33 20.55 0 bottom
C346  4.7u/6.3v_6  [CC0603]  22.22 13.95 270 bottom
C347  0.01u/16v_2  [CC0201_S]  23.18 13.7 270 bottom
C348  *0.1u/16v_2  [CC0201_S]  21.07 13.7 270 bottom
C349  *0.1u/16v_2  [CC0201_S]  20.44 13.7 270 bottom
C350  0.01u/16v_2  [CC0201_S]  19.8 13.7 90 bottom
C351  0.01u/16v_2  [CC0201_S]  19.17 13.7 90 bottom
C352  0.01u/16v_2  [CC0201_S]  17.65 13.7 270 bottom
C353  0.01u/16v_2  [CC0201_S]  17.01 13.7 90 bottom
C354  0.01u/16v_2  [CC0201_S]  16.38 13.7 90 bottom
C355  4.7u/6.3v_6  [CC0603]  27.55 13.57 270 bottom
C356  *4.7u/6.3v_6  [CC0603]  5.71 13.44 270 bottom
C357  *4.7u/6.3v_6  [CC0603]  4.44 13.44 270 bottom
C358  0.01u/16v_2  [CC0201_S]  28.59 13.01 270 bottom
C359  *0.1u/10v_2  [CC0201_S]  26.23 12.96 270 bottom
C360  0.01u/16v_2  [CC0201_S]  3.34 12.63 270 bottom
C361  *1000p/50v_4  [CC0402]  209.24 74.68 180 bottom
C362  10u/6.3v_6  [CC0603]  234.97 116.62 90 bottom
C363  0.01u/16v_4  [CC0402]  231.77 116.95 270 bottom
C364  0.1u/10v_2  [CC0201_S]  232.96 116.41 90 bottom
C365  0.1u/10v_2  [CC0201_S]  233.6 116.41 90 bottom
C366  22u/6.3vs_8  [CC0805]  266.11 113.04 180 bottom
CN1  *sec_bsh-030-01-l-d-a-tr  [BSH-030-01-L-D-A-TR-60P-LDH]  10.33 71.86 270 top
CN2  *aces_88511-180n  [88511-180N-18P-L]  77.97 55.22 90 top
CN3  camera conn  [50208-01001-001-10P-L]  190.49 107.85 0 bottom
CN4  rtc_conn  [ML1220-SMT]  228.51 102.9 90 bottom
CN5  mini pcie h=4.0  [MINIPCI-MPCET-SSC10-TS10-52P]  273.17 96.63 270 bottom
CN6  gs12407-11141-9f  [GS12407-11141-9H-40P-R]  250.5 86.4 180 bottom
CN7  gs12401-1011-9h  [50406-02071-001-20P-R]  7 84.9 90 bottom
CN8  fh35c-31s-0.3shw(50)  [FH35C-31S-0_3SHW-31P-LDH]  192.12 83.67 180 bottom
CN9  pmpcr0-08mnbs2zz4h5  [51278-00941-001-9P-L]  159.4 81.22 180 bottom
CN10  power btn conn  [50505-00441-001-4P-L]  286.75 76.15 270 bottom
CN11  touch screen  [88194-1001-10P-L]  267.65 76 270 bottom
CN12  touch screen  [50505-00641-V01-6P-L]  5.75 69.9 90 bottom
CN13  usb ffc conn  [196090-16021-3-16P-L-SMT]  55.1 21.4 180 bottom
CN14  mini sata h=4.0  [MINIPCI-MPCET-SSC10-TS10-52P]  16 2.2 180 bottom
D1  bat54c  [SOT23_213-3_3-2]  221.23 112.63 270 bottom
D2  *1ss355  [DSM]  198.54 111.82 90 bottom
D3  1ss355  [DSM]  214.06 111.21 90 bottom
D4  mek500v-40  [DSM]  197.48 103.1 180 bottom
D5  rb501v-40  [DSM]  18.79 99.8 180 bottom
D6  *ch501h-40pt  [DSM]  194.35 97.9 270 bottom
D7  *rb501v-40  [DSM]  17.77 91.04 90 bottom
D8  0.1u/10v_2  [DSM]  200.12 90.58 90 bottom
D9  rb500v-40  [DSM]  13.25 89.57 180 bottom
D10  mek500v-40  [DSM]  229.76 85.07 180 bottom
EC1  *0.1u/10v_2  [CC0201_S]  31.49 109.58 270 bottom
EC2  *0.1u/10v_2  [CC0201_S]  39.11 103.23 90 bottom
EC3  *0.1u/10v_2  [CC0201_S]  40.28 101.71 0 bottom
EC4  *0.1u/10v_2  [CC0201_S]  101.21 100.59 270 bottom
EC5  *0.1u/10v_2  [CC0201_S]  74.92 100.44 180 bottom
EC6  *0.1u/10v_2  [CC0201_S]  24.2 98.1 90 bottom
EC7  *0.1u/10v_2  [CC0201_S]  26.41 91.67 0 bottom
EC8  *0.1u/10v_2  [CC0201_S]  80.26 89.77 90 bottom
EC9  *0.1u/10v_2  [CC0201_S]  137.66 88.88 180 bottom
EC10  18p/50v_4  [CC0402]  100.83 79.99 0 bottom
EC11  *0.1u/10v_2  [CC0201_S]  12.06 67.42 180 bottom
EC12  *0.1u/10v_2  [CC0201_S]  3.29 62.59 0 bottom
EC13  18p/50v_4  [CC0402]  79.65 44.1 0 bottom
EC14  18p/50v_4  [CC0402]  79.65 43.08 0 bottom
EC15  *0.1u/10v_2  [CC0201_S]  14.09 13.57 180 bottom
FAN1  power btn conn  [50505-00441-001-4P-L]  78.5 25.15 0 bottom
H1  *h-te354x299bc91d91p2  [H-TE354X299BC91D91P2]  243.5 118.9 180 bottom
H2  *h-te354x339bc91d91p2  [H-TE354X339BC91D91P2]  103.5 118.9 180 bottom
H3  h-te354x339bc138d138p2  [H-TE354X339BC138D138P2]  170.5 109.9 180 bottom
H4  h-te473x378bc138d138p2  [H-TE473X378BC138D138P2]  7.5 108.9 180 bottom
H5  h-tc236ic142bc142d142p2  [H-TC236IC142BC142D142P2]  140.5 102.52 180 bottom
H6  h-tc236ic142bc142d142p2  [H-TC236IC142BC142D142P2]  68.5 84.4 180 bottom
H7  h-tc236ic142bc142d142p2  [H-TC236IC142BC142D142P2]  90.5 82.52 180 bottom
H8  h-te354x366bc138d138p2  [H-TE354X366BC138D138P2]  231.8 76.9 180 bottom
H9  h-tc236ic142bc142d142p2  [H-TC236IC142BC142D142P2]  18.5 68.4 180 bottom
H10  h-te413x295bc142d142p2  [H-TE413X295BC142D142P2]  156.3 67.8 180 bottom
H11  h-te315x354bc138d138p2  [H-TE315X354BC138D138P2]  3.5 22.9 180 bottom
H14  *h-c91d91n  [H-C91D91N]  55 14.9 0 top
JDIM1  ddr3-dimm1_h=4.0_rvs  [DDR-DDRRK-20401-TP4B-204P-RUV]  37.1 33.3 180 bottom
L1  blm18ba470sn1d  [RC0603]  224.68 112.91 180 bottom
L2  *mcm2012b900gbe  [CHOKE-WCM2012-4P]  195.62 103.1 270 bottom
L3  fcm1608kf-301t02  [RC0603]  191.58 102.29 270 bottom
L4  fcm1608kf-301t02  [RC0603]  190.31 102.29 270 bottom
L5  *0_8/s  [SHORT0805]  4.36 99.62 180 bottom
L6  2.2uh/500ma_6  [RC0603]  45.97 98.79 270 bottom
L7  0_6  [RC0603]  44.7 98.79 270 bottom
L8  ti160808u600  [RC0603]  10.28 98.4 180 bottom
L9  2.2uh/500ma_6  [RC0603]  60.39 98.25 180 bottom
L10  2.2uh/500ma_6  [RC0603]  57.22 96.78 0 bottom
L11  2.2uh/500ma_6  [RC0603]  52.32 96.37 180 bottom
L12  *mcm2012b900gbe  [CHOKE-WCM2012-4P]  259.17 93.2 90 bottom
L13  blm18pg181sn1d(180,1.5a)_6  [RC0603]  204.54 85.68 180 bottom
L14  0_6  [RC0603]  213.48 84.18 180 bottom
L15  *0_6  [RC0603]  208.63 84.18 270 bottom
L16  hcb1608kf-181t15_6  [RC0603]  225.93 83.67 0 bottom
L17  *hcb1608kf-181t15_6  [RC0603]  225.93 82.4 0 bottom
L18  hcb1608kf-181t15_6  [RC0603]  224.53 79.1 90 bottom
NOREF  -  []  -0.9 -30.75 0 top
NOREF#2  -  []  52.19 44.96 0 top
NOREF#3  -  []  159.05 -17.7 0 top
NOREF#4  -  []  22.98 46.08 180 bottom
PC1  *15u 25v  [CC3528]  62.48 116.31 270 top
PC2  *15u 25v  [CC3528]  65.78 116.31 270 top
PC3  *15u 25v  [CC3528]  90.67 116.31 270 top
PC4  15u 25v  [CC3528]  94.23 116.31 270 top
PC5  *0.1u/10v_4  [CC0402]  77.59 116.82 90 bottom
PC6  0.1u/10v_4  [CC0402]  74.16 116.82 270 bottom
PC7  0.1u/25v_4  [CC0402]  89.65 115.93 90 bottom
PC8  22u/6.3v_8  [CC0805]  95.5 115.55 270 bottom
PC9  22u/6.3v_8  [CC0805]  93.46 115.55 270 bottom
PC10  22u/6.3v_8  [CC0805]  91.43 115.55 270 bottom
PC11  *680p/50v_4  [CC0402]  62.73 115.17 0 bottom
PC12  1000p/50v_4  [CC0402]  60.57 115.17 180 bottom
PC13  470p/50v_4  [CC0402]  65.27 114.53 270 bottom
PC14  270p/50v_4  [CC0402]  62.73 114.15 0 bottom
PC15  4.7u/25v_8  [CC0805]  86.86 113.9 90 bottom
PC16  4.7u/25v_8  [CC0805]  84.83 113.9 90 bottom
PC17  1u/6.3v_4  [CC0402]  74.67 113.9 180 bottom
PC18  2.2u/6.3v_6  [CC0603]  59.78 112.96 180 bottom
PC19  2200p/50v_4  [CC0402]  83.3 112.5 270 bottom
PC20  0.1u/25v_4  [CC0402]  82.29 112.5 270 bottom
PC21  0.1u/25v_4  [CC0402]  72.51 112.25 90 bottom
PC22  *1500p/50v_4  [CC0402]  68.06 112.25 270 bottom
PC23  *0.1u/10v_4  [CC0402]  105.28 111.74 90 bottom
PC24  1u/6.3v_4  [CC0402]  101.72 111.74 90 bottom
PC25  0.1u/25v_4  [CC0402]  99.43 111.74 90 bottom
PC26  10u/6.3v_6  [CC0603]  149.6 111.23 180 bottom
PC27  0.01u/25v_4  [CC0402]  57.65 111.23 270 bottom
PC28  *2200p/50v_4  [CC0402]  154.17 110.85 270 bottom
PC29  0.1u/10v_4  [CC0402]  123.51 110.85 90 bottom
PC30  10p/50v_4  [CC0402]  66.54 110.72 0 bottom
PC31  330p/50v_4  [CC0402]  68.57 110.6 0 bottom
PC32  *22u/6.3v_8  [CC0805]  29.86 110.24 270 bottom
PC33  *22u/6.3v_8  [CC0805]  23.84 110.24 270 bottom
PC34  *22u/6.3v_8  [CC0805]  21.84 110.24 270 bottom
PC35  0.1u/25v_4  [CC0402]  141.91 110.22 180 bottom
PC36  2200p/50v_4  [CC0402]  183.89 109.83 270 bottom
PC37  1000p/50v_4  [CC0402]  182.75 109.83 270 bottom
PC38  0.1u/25v_4  [CC0402]  181.6 109.83 90 bottom
PC39  0.1u/25v_4  [CC0402]  56.51 109.63 180 bottom
PC40  *2200p/50v_4  [CC0402]  49.01 109.58 180 bottom
PC41  *2200p/50v_4  [CC0402]  176.55 109.28 270 bottom
PC42  *2200p/50v_4  [CC0402]  79.62 108.82 90 bottom
PC43  0.01u/25v_4  [CC0402]  218.79 108.54 0 bottom
PC44  0.1u/10v_4  [CC0402]  133.47 108.31 90 bottom
PC45  10u/6.3v_6  [CC0603]  131.01 108.31 180 bottom
PC46  0.1u/25v_4  [CC0402]  112.51 108.31 90 bottom
PC47  *2200p/50v_4  [CC0402]  68.45 108.18 0 bottom
PC48  4.7u/25v_8  [CC0805]  110.74 108.06 90 bottom
PC49  4.7u/25v_8  [CC0805]  108.7 108.06 90 bottom
PC50  0.1u/25v_4  [CC0402]  154.68 107.93 270 bottom
PC51  0.1u/25v_4  [CC0402]  107.08 107.93 270 bottom
PC52  2200p/50v_4  [CC0402]  105.94 107.93 270 bottom
PC53  0.22u/25v_6  [CC0603]  56.51 107.83 270 bottom
PC54  0.1u/25v_4  [CC0402]  147.57 107.42 90 bottom
PC55  2200p/50v_4  [CC0402]  146.55 107.42 90 bottom
PC56  4.7u/25v_8  [CC0805]  144.9 107.29 270 bottom
PC57  4.7u/25v_8  [CC0805]  142.87 107.29 270 bottom
PC58  *220uf_6.3v_7343  [CC7343-2_15H]  88.13 107.24 90 bottom
PC59  0.1u/10v_4  [CC0402]  131.31 106.91 0 bottom
PC60  1000p/50v_4  [CC0402]  66.92 106.91 90 bottom
PC61  1u/6.3v_4  [CC0402]  65.65 106.91 90 bottom
PC62  22u/6.3v_8  [CC0805]  84.68 106.15 270 bottom
PC63  *22u/6.3v_8  [CC0805]  82.64 106.15 270 bottom
PC64  0.01u/50v_4  [CC0402]  57.4 106.02 0 bottom
PC65  *4.7u/25v_8  [CC0805]  52.57 106.02 270 bottom
PC66  4.7u/25v_8  [CC0805]  50.41 106.02 270 bottom
PC67  4.7u/25v_8  [CC0805]  48.38 106.02 270 bottom
PC68  4.7u/6.3v_6  [CC0603]  126.81 105.77 90 bottom
PC69  22u/6.3v_8  [CC0805]  80.61 105.52 270 bottom
PC70  22u/6.3v_8  [CC0805]  78.58 105.52 270 bottom
PC71  *22u/6.3v_8  [CC0805]  22.22 105.52 0 bottom
PC72  *22u/6.3v_8  [CC0805]  26.28 104.75 0 bottom
PC73  *0.1u/10v_4  [CC0402]  146.55 104.25 0 bottom
PC74  0.1u/25v_4  [CC0402]  41.39 104.25 270 bottom
PC75  0.1u/25v_4  [CC0402]  106.65 104.22 180 bottom
PC76  22u/6.3v_8  [CC0805]  94.81 104.12 90 bottom
PC77  *2200p/50v_4  [CC0402]  98.54 103.99 90 bottom
PC78  0.1u/10v_4  [CC0402]  96.33 103.94 90 bottom
PC79  1u/6.3v_4  [CC0402]  150.36 103.74 270 bottom
PC80  *0.1u/10v_4  [CC0402]  100.07 103.61 90 bottom
PC81  4.7u/25v_8  [CC0805]  183.51 103.48 0 bottom
PC82  *22u/6.3v_8  [CC0805]  22.22 103.48 0 bottom
PC83  0.1u/25v_4  [CC0402]  168.39 103.23 0 bottom
PC84  10u/6.3v_6  [CC0603]  101.72 103.23 270 bottom
PC85  0.1u/25v_4  [CC0402]  106.65 103.18 180 bottom
PC86  2200p/50v_4  [CC0402]  42.16 102.67 180 bottom
PC87  1u/16v_4  [CC0402]  172.46 102.34 180 bottom
PC88  0.1u/25v_4  [CC0402]  170.43 102.34 180 bottom
PC89  0.1u/25v_4  [CC0402]  166.36 102.09 0 bottom
PC90  0.1u/10v_4  [CC0402]  53.97 101.96 270 bottom
PC91  1u/35v_6  [CC0603]  106.55 101.86 0 bottom
PC92  0.1u/10v_4  [CC0402]  61.71 101.68 180 bottom
PC93  *22u/6.3v_8  [CC0805]  21.96 101.45 0 bottom
PC94  0.1u/10v_4  [CC0402]  86.1 101.2 90 bottom
PC95  0.1u/10v_4  [CC0402]  146.04 101.07 270 bottom
PC96  0.47u/25v_6  [CC0603]  106.55 100.69 180 bottom
PC97  0.1u/25v_4  [CC0402]  156.46 100.56 90 bottom
PC98  0.1u/10v_4  [CC0402]  97.12 100.56 270 bottom
PC99  *10u/6.3v_6  [CC0603]  100.07 100.46 270 bottom
PC100  0.1u/10v_4  [CC0402]  66.46 100.44 270 bottom
PC101  1u/16v_4  [CC0402]  113.89 99.67 270 bottom
PC102  *22u/6.3v_8  [CC0805]  21.96 99.42 0 bottom
PC103  0.047u/25v_4  [CC0402]  173.47 99.29 90 bottom
PC104  *0.01u/25v_4  [CC0402]  54.22 98.4 90 bottom
PC105  *0.1u/10v_4  [CC0402]  53.21 98.4 90 bottom
PC106  *220uf_6.3v_7343  [CC7343-2_15H]  153.43 98.28 270 bottom
PC107  *10u/6.3v_6  [CC0603]  56.13 98.15 0 bottom
PC108  22u/6.3v_8  [CC0805]  149.73 97.26 90 bottom
PC109  22u/6.3v_8  [CC0805]  147.69 97.26 90 bottom
PC110  22u/6.3v_8  [CC0805]  145.66 97.26 90 bottom
PC111  22u/6.3v_8  [CC0805]  143.63 97.26 90 bottom
PC112  0.1u/10v_4  [CC0402]  91.31 96.88 270 bottom
PC113  100p/50v_4  [CC0402]  165.6 96.75 90 bottom
PC114  0.022u/50v_4  [CC0402]  96.66 95.89 90 bottom
PC115  0.47u/25v_6  [CC0603]  173.22 95.64 90 bottom
PC116  2200p/50v_4  [CC0402]  138.17 95.61 0 bottom
PC117  0.1u/25v_4  [CC0402]  171.57 95 180 bottom
PC118  0.01u/50v_4  [CC0402]  164.46 94.98 90 bottom
PC119  2200p/50v_4  [CC0402]  183.38 94.34 180 bottom
PC120  *0.1u/10v_4  [CC0402]  165.6 94.21 90 bottom
PC121  0.1u/25v_4  [CC0402]  173.47 93.83 180 bottom
PC122  0.1u/25v_4  [CC0402]  171.44 93.83 180 bottom
PC123  0.1u/10v_4  [CC0402]  143.5 92.82 0 bottom
PC124  *2200p/50v_4  [CC0402]  165.09 92.31 180 bottom
PC125  0.1u/10v_4  [CC0402]  137.66 91.67 90 bottom
PC126  *10u/6.3v_6  [CC0603]  136.39 91.42 90 bottom
PC127  10u/25v_8  [CC0805]  184.65 89.13 90 bottom
PC128  10u/25v_8  [CC0805]  182.62 89.13 90 bottom
PC129  0.1u/25v_4  [CC0402]  181.09 88.5 90 bottom
PC130  0.1u/25v_4  [CC0402]  180.08 88.5 90 bottom
PC131  0.01u/25v_4  [CC0402]  168.27 88.5 90 bottom
PC132  0.022u/50v_6  [CC0603]  159.76 88.37 180 bottom
PC133  0.1u/25v_4  [CC0402]  157.22 88.24 180 bottom
PC134  0.1u/25v_4  [CC0402]  178.55 87.99 180 bottom
PC135  *100p/50v_4  [CC0402]  174.11 87.86 180 bottom
PC136  *100p/50v_4  [CC0402]  171.95 87.86 0 bottom
PC137  *0.1u/10v_4  [CC0402]  13.58 26.27 180 bottom
PC138  0.01u/25v_4  [CC0402]  16.5 24.74 270 bottom
PC139  0.1u/10v_4  [CC0402]  13.07 24.74 270 bottom
PC140  0.22u/10v_4  [CC0402]  11.3 24.24 180 bottom
PC141  10u/6.3v_6  [CC0603]  9.64 23.98 270 bottom
PC142  1u/6.3v_4  [CC0402]  17.01 21.7 180 bottom
PC143  0.1u/25v_4  [CC0402]  17.01 20.68 0 bottom
PC144  4.7u/25v_8  [CC0805]  21.07 20.55 270 bottom
PC145  4.7u/25v_8  [CC0805]  19.07 20.55 270 bottom
PC146  330u_2v_7343  [CC7343-2_15H]  36.57 19.66 270 bottom
PC147  *10u/6.3v_6  [CC0603]  9.14 18.78 0 bottom
PC148  0.1u/10v_4  [CC0402]  39.49 17.38 90 bottom
PC149  0.1u/25v_4  [CC0402]  21.46 17.38 270 bottom
PC150  2200p/50v_4  [CC0402]  20.44 17.38 270 bottom
PC151  0.1u/25v_4  [CC0402]  15.11 16.49 0 bottom
PC152  *2200p/50v_4  [CC0402]  25.27 13.82 270 bottom
PD1  p4smaj20a  [D-DO-214AC]  68.96 116.11 90 top
PD2  *bat54c  [SOT23_213-3_3-2]  119.52 109.61 90 bottom
PD3  p4smaj20a  [D-DO-214AC]  160.65 103.99 0 bottom
PD4  rb501v-40  [DSM]  171.65 103.74 270 bottom
PD5  mew316-d3-g  [DSM]  134.03 103.31 270 bottom
PD6  sx34  [D-DO-214AC]  187.27 92.44 0 bottom
PD7  pdz5.6b  [DSM]  175.25 91.17 180 bottom
PD8  pdz5.6b  [DSM]  173.35 91.17 180 bottom
PJP1  *power_jp/s  [SHORT-SOLDERJUMPER-3]  83.81 102.47 270 bottom
PJP2  *power_jp/s  [SHORT-SOLDERJUMPER-3]  92.07 101.58 270 bottom
PJP3  *power_jp/s  [SHORT-SOLDERJUMPER-3]  140.84 97.01 270 bottom
PJP4  *power_jp/s  [SHORT-SOLDERJUMPER-3]  40.94 20.73 0 bottom
PL1  *0_8/s  [SHORT0805]  87.37 116.69 180 bottom
PL2  2.2uh/1.3a_2520  [L3_2X2_5-1_55]  129.66 110.98 0 bottom
PL3  *0_8/s  [SHORT0805]  111.88 110.85 180 bottom
PL4  4.7uh/5.5a  [CHOKE-MPL73-1R5]  159.63 109.58 270 bottom
PL5  4.7uh/5.5a  [CHOKE-MPL73-1R5]  94.73 109.45 180 bottom
PL6  *0_8/s  [SHORT0805]  140.71 107.81 270 bottom
PL7  0.22uh/29a_7x7x1.8  [CHOKE-ETQP4LR36AFM]  36.95 107.68 180 bottom
PL8  *0_8/s  [SHORT0805]  54.75 107.07 90 bottom
PL9  1uh/11a(em-10am05v06)  [CHOKE-MPL73-1R5]  73.88 106.48 270 bottom
PL10  80/5a  [RC0805]  59.56 101.45 270 bottom
PL11  4.7uh/5.5a(em-47am05v08)  [CHOKE-MPL73-1R5]  178.05 101.33 270 bottom
PL12  80/5a  [RC0805]  148.94 84.82 270 bottom
PL13  80/5a  [RC0805]  146.91 84.82 270 bottom
PL14  0.82uh/13a(em-82bm05v04)  [CHOKE-MPL73-1R5]  29.96 20.17 0 bottom
PL15  *0_8/s  [SHORT0805]  18.03 17.76 0 bottom
PQ1  emb20n03v  [PG-TSDSON-8-8P-R]  178.91 107.93 180 bottom
PQ2  emb20n03v  [PG-TSDSON-8-8P-R]  182.75 106.79 270 bottom
PQ3  rjk03s3dpa  [POWER-5X6-1_27-7P]  44.7 106.61 180 bottom
PQ4  *metr3904-g  [SOT23_213-3_3-2]  135.81 106.13 0 bottom
PQ5  *emb20n03v  [PG-TSDSON-8-8P-R]  56.63 100.82 0 bottom
PQ6  tpca8064-h  [SO-8FL-5P]  185.03 99.67 0 bottom
PQ7  qm3016d  [TO252_134-9_9-4_57-SMT]  160.52 98.91 270 bottom
PQ8  *2n7002k  [SOT23_213-3_3-2]  134.76 98.3 180 bottom
PQ9  2n7002k  [SOT23_213-3_3-2]  190.11 98 90 bottom
PQ10  emb20n03v  [PG-TSDSON-8-8P-R]  93.97 97.52 90 bottom
PQ11  emb20n03v  [PG-TSDSON-8-8P-R]  140.35 93.05 270 bottom
PQ12  mmdt2907a  [SOT363-2_1-65-6P]  147.57 92.21 0 bottom
PQ13  emb20p03v  [PG-TSDSON-8-8P-R]  151.25 89.64 180 bottom
PQ14  mdv1595surh  [PG-TSDSON-8-8P-R]  24.12 22.33 270 bottom
PQ15  emb20n03v  [PG-TSDSON-8-8P-R]  24.12 18.14 90 bottom
PR1  287k/f_6  [RC0603]  58.67 117.33 0 bottom
PR2  121k/f_4  [RC0402]  64.76 116.95 270 bottom
PR3  165k/f_4  [RC0402]  63.24 116.95 270 bottom
PR4  *0_4/s  [SHORT0402]  76.45 116.82 90 bottom
PR5  *0_4/s  [SHORT0402]  75.3 116.82 90 bottom
PR6  100k/f_4  [RC0402]  72.99 116.82 90 bottom
PR7  *0_2/s  [SHORT0201]  78.73 116.44 90 bottom
PR8  2.4k/f_4  [RC0402]  81.17 116.31 270 bottom
PR9  7.68k/f_4  [RC0402]  80.13 116.31 270 bottom
PR10  10/f_4  [RC0402]  60.57 116.18 0 bottom
PR11  8.25k/f_4  [RC0402]  56.63 114.66 90 bottom
PR12  15.4k/f_4  [RC0402]  66.29 114.53 90 bottom
PR13  24.3k/f_4  [RC0402]  64.25 114.53 90 bottom
PR14  100k/f_4  [RC0402]  60.57 114.15 180 bottom
PR15  69.8k/f_4  [RC0402]  57.65 113.26 270 bottom
PR16  0_6  [RC0603]  74.41 112.76 180 bottom
PR17  *0_4/s  [SHORT0402]  56.63 112.63 90 bottom
PR18  0_4  [RC0402]  69.21 112.25 270 bottom
PR19  6.04k/f_4  [RC0402]  66.92 112.25 90 bottom
PR20  18.7k/f_4  [RC0402]  65.78 112.25 90 bottom
PR21  0_6  [RC0603]  100.58 111.99 90 bottom
PR22  *0_4/s  [SHORT0402]  106.42 111.74 90 bottom
PR23  *330k/f_4  [RC0402]  104.13 111.74 270 bottom
PR24  *665k/f_4  [RC0402]  103.12 111.74 90 bottom
PR25  *0_4/s  [SHORT0402]  152.01 111.36 0 bottom
PR26  *0_4/s  [SHORT0402]  146.68 111.23 180 bottom
PR27  *0_4  [RC0402]  144.52 111.23 0 bottom
PR28  th05-3l104fr  [RC0402]  41.39 110.85 270 bottom
PR29  220k_6 ntc  [RC0603]  32.5 110.72 90 bottom
PR30  *2.2_6  [RC0603]  155.31 110.6 90 bottom
PR31  1k/f_4  [RC0402]  66.54 109.71 180 bottom
PR32  49.9/f_4  [RC0402]  68.57 109.45 180 bottom
PR33  *1m_4  [RC0402]  135.63 109.2 90 bottom
PR34  *1m_4  [RC0402]  134.61 109.2 90 bottom
PR35  *0_4/s  [SHORT0402]  123.51 108.69 270 bottom
PR36  *2.2_6  [RC0603]  78.35 108.67 270 bottom
PR37  *0_4/s  [SHORT0402]  66.41 108.44 0 bottom
PR38  *2.2_6  [RC0603]  48.63 108.31 0 bottom
PR39  *0_2/s  [SHORT0201]  38.6 107.68 0 bottom
PR40  *0_2/s  [SHORT0201]  35.3 107.68 180 bottom
PR41  *0_4/s  [SHORT0402]  68.45 107.17 0 bottom
PR42  *2.2_6  [RC0603]  176.32 106.89 90 bottom
PR43  0_6  [RC0603]  153.54 106.53 90 bottom
PR44  12.4k/f_4  [RC0402]  133.47 106.28 270 bottom
PR45  *0_4/s  [SHORT0402]  68.45 106.15 0 bottom
PR46  *0_4/s  [SHORT0402]  125.61 105.97 270 bottom
PR47  10k/f_4  [RC0402]  124.59 105.95 270 bottom
PR48  15k/f_4  [RC0402]  123.45 105.95 270 bottom
PR49  *0_6/s  [SHORT0603]  128.08 105.77 270 bottom
PR50  22_6  [RC0603]  106.55 105.36 0 bottom
PR51  *0_4  [RC0402]  110.94 105.34 180 bottom
PR52  *0_4/s  [SHORT0402]  65.91 104.78 270 bottom
PR53  *0_4  [RC0402]  64.89 104.78 270 bottom
PR54  *0_4/s  [SHORT0402]  63.87 104.78 270 bottom
PR55  *0_4/s  [SHORT0402]  62.86 104.78 270 bottom
PR56  *0_4/s  [SHORT0402]  60.52 104.78 270 bottom
PR57  *0_4/s  [SHORT0402]  59.45 104.78 270 bottom
PR58  75k/f_4  [RC0402]  132.96 104.75 180 bottom
PR59  *0_2/s  [SHORT0201]  131.18 104.63 0 bottom
PR60  *0_4/s  [SHORT0402]  58.44 104.5 270 bottom
PR61  *10k/f_4  [RC0402]  57.27 104.5 90 bottom
PR62  *330k/f_4  [RC0402]  148.71 104.25 0 bottom
PR63  *2.2_6  [RC0603]  97.45 104.25 270 bottom
PR64  1k/f_4  [RC0402]  56 104.25 90 bottom
PR65  *0_4  [RC0402]  113.53 104.15 0 bottom
PR66  2.2_6  [RC0603]  68.06 103.87 270 bottom
PR67  *0_4  [RC0402]  104.08 103.48 90 bottom
PR68  *0_4/s  [SHORT0402]  102.94 103.48 270 bottom
PR69  1_6  [RC0603]  48.63 103.36 0 bottom
PR70  *665k/f_4  [RC0402]  148.71 103.23 180 bottom
PR71  *0_4/s  [SHORT0402]  146.55 103.23 180 bottom
PR72  100k/f_4  [RC0402]  166.36 103.1 180 bottom
PR73  *0_4/s  [SHORT0402]  113.53 103.08 180 bottom
PR74  *0_4/s  [SHORT0402]  66.92 102.98 90 bottom
PR75  *75/f_4  [RC0402]  64.76 102.49 0 bottom
PR76  *82k/f_4  [RC0402]  148.46 102.21 180 bottom
PR77  *0_4/s  [SHORT0402]  113.48 101.88 0 bottom
PR78  *0_2/s  [SHORT0201]  94.23 101.83 180 bottom
PR79  *0_4/s  [SHORT0402]  168.9 101.58 270 bottom
PR80  *0_4/s  [SHORT0402]  167.89 101.58 270 bottom
PR81  69.8k/f_4  [RC0402]  135.37 101.4 90 bottom
PR82  *88.7k/f_4  [RC0402]  134.21 101.4 90 bottom
PR83  430k/f_4  [RC0402]  133.09 101.4 270 bottom
PR84  10k/f_4  [RC0402]  103.42 101.38 0 bottom
PR85  *0_2/s  [SHORT0201]  87.24 101.33 90 bottom
PR86  0_6  [RC0603]  172.59 101.07 0 bottom
PR87  *100k/f_4  [RC0402]  166.36 101.07 180 bottom
PR88  *0_2/s  [SHORT0201]  148.33 100.94 270 bottom
PR89  130/f_4  [RC0402]  65.45 100.94 270 bottom
PR90  *75/f_4  [RC0402]  64.43 100.94 270 bottom
PR91  *100k/f_4  [RC0402]  110.86 99.37 0 bottom
PR92  *750k/f_4  [RC0402]  108.81 99.37 0 bottom
PR93  *0_4  [RC0402]  106.7 99.37 180 bottom
PR94  *1m_4  [RC0402]  132.2 99.29 90 bottom
PR95  *0_4/s  [SHORT0402]  165.6 99.17 90 bottom
PR96  *0_4/s  [SHORT0402]  164.58 99.17 90 bottom
PR97  54.9/f_4  [RC0402]  65.4 98.91 90 bottom
PR98  *1m_4  [RC0402]  132.2 97.26 270 bottom
PR99  10/f_4  [RC0402]  164.46 97.01 270 bottom
PR100  22_8  [RC0805]  174.92 96.04 270 bottom
PR101  *0_2/s  [SHORT0201]  179.02 95.61 90 bottom
PR102  470_8  [RC0805]  189.86 95.1 180 bottom
PR103  rc1206-r020  [F3_2X1_65-2_8]  179.02 94.87 270 bottom
PR104  2k/f_4  [RC0402]  181.22 94.34 0 bottom
PR105  *0_2/s  [SHORT0201]  179.02 94.21 270 bottom
PR106  4.02k/f_4  [RC0402]  169.92 93.96 90 bottom
PR107  2k/f_4  [RC0402]  168.9 93.96 90 bottom
PR108  100k/f_4  [RC0402]  167.89 93.96 90 bottom
PR109  100k/f_4  [RC0402]  166.74 93.96 270 bottom
PR110  220k_4  [RC0402]  147.06 93.96 180 bottom
PR111  1m_4  [RC0402]  145.03 93.96 180 bottom
PR112  1m_4  [RC0402]  150.23 93.32 0 bottom
PR113  1k_6  [RC0603]  153.03 93.2 180 bottom
PR114  220k_4  [RC0402]  145.41 92.44 270 bottom
PR115  *0_2/s  [SHORT0201]  147.79 88.88 0 bottom
PR116  *0_2/s  [SHORT0201]  146.32 88.88 180 bottom
PR117  rc1206-r010  [F3_2X1_65-2_8]  147.08 88.75 180 bottom
PR118  1k/f_4  [RC0402]  170.3 88.5 270 bottom
PR119  200k_4  [RC0402]  169.28 88.5 90 bottom
PR120  330_4  [RC0402]  173.6 86.21 270 bottom
PR121  330_4  [RC0402]  172.46 86.21 270 bottom
PR122  *100/f_4  [RC0402]  11.3 25.25 180 bottom
PR123  31.6k/f_4  [RC0402]  17.52 24.74 270 bottom
PR124  10k/f_4  [RC0402]  14.6 24.62 180 bottom
PR125  2.2_6  [RC0603]  16.76 19.49 0 bottom
PR126  *0_2/s  [SHORT0201]  39.49 19.03 180 bottom
PR127  120k/f_4  [RC0402]  12.06 18.01 270 bottom
PR128  47k/f_4  [RC0402]  11.04 18.01 270 bottom
PR129  *0_4/s  [SHORT0402]  13.07 17.89 270 bottom
PR130  *0_4/s  [SHORT0402]  9.39 17.51 180 bottom
PR131  *0_4/s  [SHORT0402]  13.07 15.85 270 bottom
PR132  *2.2_6  [RC0603]  26.03 15.6 180 bottom
PU1  aoz1237  [QFN23-4X4-5]  78.99 112.63 270 bottom
PU2  apw8824  [TSOP6-2_8-95]  125.93 109.58 0 bottom
PU3  ncp81101mntxg  [QFN28-4X4-4-29P-NCP81101MNTWG]  61.39 109.28 90 bottom
PU4  nb670  [QFN14-3X3-4-16P]  102.1 107.93 180 bottom
PU5  nb669  [QFN14-3X3-4-16P]  150.61 107.29 0 bottom
PU6  g5934rz1u  [TQFN20-3X3-4-21P]  110.2 102.32 270 bottom
PU7  bq24738  [PVQFN20-3_5X3_5-5-25P]  168.78 98.02 180 bottom
PU8  apw8819qai  [TQFN20-3X3-4-21P]  13.28 21.2 0 bottom
Q1  mmbt3904-7-f  [SOT23_213-3_3-2]  231.87 113.24 90 bottom
Q2  2n7002e  [SOT23_213-3_3-2]  260.95 111.18 0 bottom
Q3  2n7002e  [SOT23_213-3_3-2]  257.27 111.18 180 bottom
Q4  *metr3904-g  [SOT23_213-3_3-2]  200.4 108.97 90 bottom
Q5  dmg1012t-7(sot523)  [D-SOT523_213-1_6-1]  203.88 108.82 90 bottom
Q6  2n7002e  [SOT23_213-3_3-2]  260.95 105.95 180 bottom
Q7  me2303t1  [SOT23_213-3_3-2]  257.27 105.92 180 bottom
Q8  *metr3904-g  [SOT23_213-3_3-2]  200.4 105.39 90 bottom
Q9  2n7002k  [SOT23_213-3_3-2]  200.42 101.58 90 bottom
Q10  *2n7002  [SOT23_213-3_3-2]  77.97 100.82 180 bottom
Q11  *2n7002  [SOT23_213-3_3-2]  72.1 100.06 90 bottom
Q12  *ddtc144eua-7-f  [UMT_213-3-1_3]  260.57 98.66 0 bottom
Q13  ddtc144eua-7-f  [UMT_213-3-1_3]  260.57 95.99 0 bottom
Q14  mmbt3904t-7-f/sot523  [SOT523_213-1_6-1-3P]  192.78 94.21 0 bottom
Q15  mmbt3904t-7-f/sot523  [SOT523_213-1_6-1-3P]  194.73 93.96 0 bottom
Q16  pj4n3kdw  [SC70-2_1-65-6P]  193.16 89.77 270 bottom
Q17  metr3904-g  [SOT23_213-3_3-2]  88.56 88.09 270 bottom
Q18  *mmbt3904-7-f  [SOT23_213-3_3-2]  226.56 86.29 180 bottom
Q19  pj4n3kdw  [SC70-2_1-65-6P]  232.88 85.83 0 bottom
Q20  2n7002dw  [SC70-2_1-65-6P]  183.51 84.66 0 bottom
Q21  2n7002dw  [SC70-2_1-65-6P]  79.39 82.1 90 bottom
Q22  2n7002dw  [SC70-2_1-65-6P]  77.64 78.08 90 bottom
Q23  2n7002  [SOT23_213-3_3-2]  223 75.93 270 bottom
Q24  *metr3904-g  [SOT23_213-3_3-2]  78.63 46.56 90 bottom
Q25  dtc144eua  [UMT_213-3-1_3]  68.5 22.28 180 bottom
Q26  2n7002k  [SOT23_213-3_3-2]  68.31 17.53 0 bottom
Q27  2n7002  [SOT23_213-3_3-2]  41.93 16.92 180 bottom
Q30  pj4n3kdw  [SC70-2_1-65-6P]  181.98 81.26 90 bottom
R1  *0_4/s  [SHORT0402]  206.29 103.1 0 top
R2  *0_2  [RC0201_S]  251.71 101.83 0 top
R3  *0_2  [RC0201_S]  251.71 101.1 0 top
R4  *0_2  [RC0201_S]  252.21 99.32 0 top
R5  *0_2  [RC0201_S]  252.21 98.66 0 top
R6  *0_4/s  [SHORT0402]  233.8 91.09 270 top
R7  *0_4/s  [SHORT0402]  234.82 91.09 270 top
R8  *0_4/s  [SHORT0402]  235.48 88.7 0 top
R9  *0_4/s  [SHORT0402]  235.48 87.69 0 top
R10  *0_8/s  [SHORT0805]  214.06 79.69 180 top
R11  *0_8/s  [SHORT0805]  217.42 78.21 270 top
R12  10k_2  [RC0201_S]  222.67 115.96 0 bottom
R13  *10k_2  [RC0201_S]  221.12 115.96 180 bottom
R14  2.2k_2  [RC0201_S]  238.5 115.17 0 bottom
